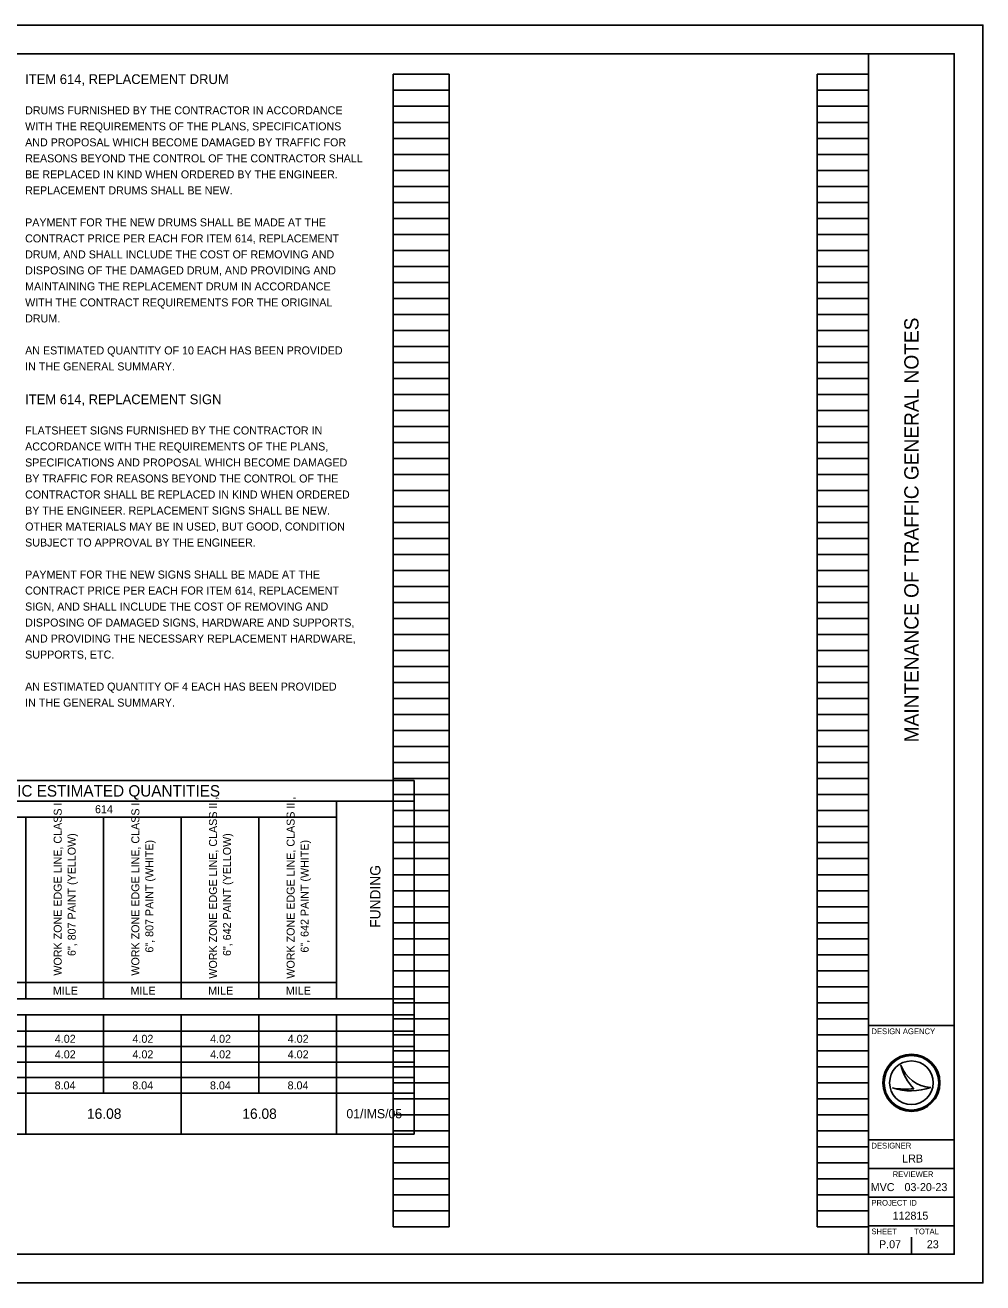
# Model space of a CAD drawing. Extents: x 0 to 154, y -283 to 22.
# Drawn here: x 17.24 to 34, y 0 to 22 of the extents above; entities that cross this region are included whole.
import ezdxf

# ---------------------------------------------------------------- set-up
doc = ezdxf.new("R2010")
doc.units = 0
for name, color, linetype in [('SH_Border', 7, 'Continuous'), ('SH_Cut_Line', 7, 'Continuous'), ('SH_Data', 7, 'Continuous'), ('SH_Text', 7, 'Continuous')]:
    doc.layers.add(name, color=color, linetype=linetype)

msp = doc.modelspace()

# ---------------------------------------------------------------- linework, layer by layer
at = {"layer": 'SH_Border'}
for p, q in [((32, 0.5), (32, 21.5)), ((32, 4.5), (33.5, 4.5)), ((32, 2.5), (33.5, 2.5)), ((32, 2), (33.5, 2)), ((32, 1.5), (33.5, 1.5)), ((32, 1), (33.5, 1))]:
    msp.add_line(p, q, dxfattribs=at)
msp.add_lwpolyline([(1.5, 21.5), (33.5, 21.5), (33.5, 0.5), (1.5, 0.5)], close=True, dxfattribs=at)
at = {"layer": 'SH_Cut_Line'}
msp.add_lwpolyline([(0, 0), (34, 0), (34, 22), (0, 22)], close=True, dxfattribs=at)
at = {"layer": 'SH_Data'}
for p, q in [((23.68, 0.98), (23.68, 21.14)), ((23.68, 21.14), (24.66, 21.14)), ((24.66, 0.98), (24.66, 21.14)), ((31.1, 0.98), (31.1, 21.14)), ((31.1, 21.14), (32, 21.14)), ((32, 0.98), (32, 21.14)), ((23.68, 20.86), (24.66, 20.86)), ((31.1, 20.86), (32, 20.86)), ((23.68, 20.58), (24.66, 20.58)), ((31.1, 20.58), (32, 20.58)), ((23.68, 20.3), (24.66, 20.3)), ((31.1, 20.3), (32, 20.3)), ((23.68, 20.02), (24.66, 20.02)), ((31.1, 20.02), (32, 20.02)), ((23.68, 19.74), (24.66, 19.74)), ((31.1, 19.74), (32, 19.74)), ((23.68, 19.46), (24.66, 19.46)), ((31.1, 19.46), (32, 19.46)), ((23.68, 19.18), (24.66, 19.18)), ((31.1, 19.18), (32, 19.18)), ((23.68, 18.9), (24.66, 18.9)), ((31.1, 18.9), (32, 18.9)), ((23.68, 18.62), (24.66, 18.62)), ((31.1, 18.62), (32, 18.62)), ((23.68, 18.34), (24.66, 18.34)), ((31.1, 18.34), (32, 18.34)), ((23.68, 18.06), (24.66, 18.06)), ((31.1, 18.06), (32, 18.06)), ((23.68, 17.78), (24.66, 17.78)), ((31.1, 17.78), (32, 17.78)), ((23.68, 17.5), (24.66, 17.5)), ((31.1, 17.5), (32, 17.5)), ((23.68, 17.22), (24.66, 17.22)), ((31.1, 17.22), (32, 17.22)), ((23.68, 16.94), (24.66, 16.94)), ((31.1, 16.94), (32, 16.94)), ((23.68, 16.66), (24.66, 16.66)), ((31.1, 16.66), (32, 16.66)), ((23.68, 16.38), (24.66, 16.38)), ((31.1, 16.38), (32, 16.38)), ((23.68, 16.1), (24.66, 16.1)), ((31.1, 16.1), (32, 16.1)), ((23.68, 15.82), (24.66, 15.82)), ((31.1, 15.82), (32, 15.82)), ((23.68, 15.54), (24.66, 15.54)), ((31.1, 15.54), (32, 15.54)), ((23.68, 15.26), (24.66, 15.26)), ((31.1, 15.26), (32, 15.26)), ((23.68, 14.98), (24.66, 14.98)), ((31.1, 14.98), (32, 14.98)), ((23.68, 14.7), (24.66, 14.7)), ((31.1, 14.7), (32, 14.7)), ((23.68, 14.42), (24.66, 14.42)), ((31.1, 14.42), (32, 14.42)), ((23.68, 14.14), (24.66, 14.14)), ((31.1, 14.14), (32, 14.14)), ((23.68, 13.86), (24.66, 13.86)), ((31.1, 13.86), (32, 13.86)), ((23.68, 13.58), (24.66, 13.58)), ((31.1, 13.58), (32, 13.58)), ((23.68, 13.3), (24.66, 13.3)), ((31.1, 13.3), (32, 13.3)), ((23.68, 13.02), (24.66, 13.02)), ((31.1, 13.02), (32, 13.02)), ((23.68, 12.74), (24.66, 12.74)), ((31.1, 12.74), (32, 12.74)), ((23.68, 12.46), (24.66, 12.46)), ((31.1, 12.46), (32, 12.46)), ((23.68, 12.18), (24.66, 12.18)), ((31.1, 12.18), (32, 12.18)), ((23.68, 11.9), (24.66, 11.9)), ((31.1, 11.9), (32, 11.9)), ((23.68, 11.62), (24.66, 11.62)), ((31.1, 11.62), (32, 11.62)), ((23.68, 11.34), (24.66, 11.34)), ((31.1, 11.34), (32, 11.34)), ((23.68, 11.06), (24.66, 11.06)), ((31.1, 11.06), (32, 11.06)), ((23.68, 10.78), (24.66, 10.78)), ((31.1, 10.78), (32, 10.78)), ((23.68, 10.5), (24.66, 10.5)), ((31.1, 10.5), (32, 10.5)), ((23.68, 10.22), (24.66, 10.22)), ((31.1, 10.22), (32, 10.22)), ((23.68, 9.94), (24.66, 9.94)), ((31.1, 9.94), (32, 9.94)), ((23.68, 9.66), (24.66, 9.66)), ((31.1, 9.66), (32, 9.66)), ((23.68, 9.38), (24.66, 9.38)), ((31.1, 9.38), (32, 9.38)), ((23.68, 9.1), (24.66, 9.1)), ((31.1, 9.1), (32, 9.1)), ((23.68, 8.82), (24.66, 8.82)), ((31.1, 8.82), (32, 8.82)), ((23.68, 8.54), (24.66, 8.54)), ((31.1, 8.54), (32, 8.54)), ((23.68, 8.26), (24.66, 8.26)), ((31.1, 8.26), (32, 8.26)), ((23.68, 7.98), (24.66, 7.98)), ((31.1, 7.98), (32, 7.98)), ((23.68, 7.7), (24.66, 7.7)), ((31.1, 7.7), (32, 7.7)), ((23.68, 7.42), (24.66, 7.42)), ((31.1, 7.42), (32, 7.42)), ((23.68, 7.14), (24.66, 7.14)), ((31.1, 7.14), (32, 7.14)), ((23.68, 6.86), (24.66, 6.86)), ((31.1, 6.86), (32, 6.86)), ((23.68, 6.58), (24.66, 6.58)), ((31.1, 6.58), (32, 6.58)), ((23.68, 6.3), (24.66, 6.3)), ((31.1, 6.3), (32, 6.3)), ((23.68, 6.02), (24.66, 6.02)), ((31.1, 6.02), (32, 6.02)), ((23.68, 5.74), (24.66, 5.74)), ((31.1, 5.74), (32, 5.74)), ((23.68, 5.46), (24.66, 5.46)), ((31.1, 5.46), (32, 5.46)), ((23.68, 5.18), (24.66, 5.18)), ((31.1, 5.18), (32, 5.18)), ((23.68, 4.9), (24.66, 4.9)), ((31.1, 4.9), (32, 4.9)), ((23.68, 4.62), (24.66, 4.62)), ((31.1, 4.62), (32, 4.62)), ((23.68, 4.34), (24.66, 4.34)), ((31.1, 4.34), (32, 4.34)), ((23.68, 4.06), (24.66, 4.06)), ((31.1, 4.06), (32, 4.06)), ((23.68, 3.78), (24.66, 3.78)), ((31.1, 3.78), (32, 3.78)), ((32.567, 3.81), (32.567, 3.81)), ((23.68, 3.5), (24.66, 3.5)), ((31.1, 3.5), (32, 3.5)), ((32.417, 3.41), (32.417, 3.41)), ((32.75, 3.5), (32.75, 3.5)), ((33.087, 3.419), (33.087, 3.419)), ((23.68, 3.22), (24.66, 3.22)), ((31.1, 3.22), (32, 3.22)), ((23.68, 2.94), (24.66, 2.94)), ((31.1, 2.94), (32, 2.94)), ((23.68, 2.66), (24.66, 2.66)), ((31.1, 2.66), (32, 2.66)), ((23.68, 2.38), (24.66, 2.38)), ((31.1, 2.38), (32, 2.38)), ((23.68, 2.1), (24.66, 2.1)), ((31.1, 2.1), (32, 2.1)), ((23.68, 1.82), (24.66, 1.82)), ((31.1, 1.82), (32, 1.82)), ((23.68, 1.54), (24.66, 1.54)), ((31.1, 1.54), (32, 1.54)), ((23.68, 1.26), (24.66, 1.26)), ((31.1, 1.26), (32, 1.26)), ((23.68, 0.98), (24.66, 0.98)), ((31.1, 0.98), (32, 0.98)), ((32.375, 0.675), (32.375, 0.675)), ((32.75, 0.5), (32.75, 0.8))]:
    msp.add_line(p, q, dxfattribs=at)
for radius in [0.5, 0.477, 0.477, 0.382]:
    msp.add_circle((32.75, 3.5), radius, dxfattribs=at)
for centre, radius, start, end in [((33.116, 3.998), 0.58, 198.9257, 198.9319), ((33.347, 3.97), 0.796, 191.6379, 191.6421), ((33.116, 3.998), 0.58, 198.9319, 267.1657), ((33.347, 3.97), 0.796, 191.6421, 226.0947), ((32.739, 4.37), 1.013, 251.4576, 290.0832), ((32.648, 4.654), 1.266, 259.4964, 259.4995), ((32.739, 4.37), 1.013, 251.4527, 251.4576), ((32.648, 4.654), 1.266, 259.4995, 276.6672)]:
    msp.add_arc(centre, radius, start, end, dxfattribs=at)
at = {"layer": 'SH_Text'}
for p, q in [((9.59, 8.785), (24.047, 8.785)), ((24.047, 8.785), (24.047, 2.601)), ((9.59, 8.427), (24.047, 8.427)), ((22.688, 8.427), (22.688, 4.97)), ((14.536, 8.144), (22.688, 8.144)), ((17.253, 8.144), (17.253, 4.97)), ((18.612, 8.144), (18.612, 4.97)), ((19.971, 8.144), (19.971, 4.97)), ((21.33, 8.144), (21.33, 4.97)), ((14.536, 5.253), (22.688, 5.253)), ((9.59, 4.97), (24.047, 4.97)), ((9.59, 4.688), (24.047, 4.688)), ((17.253, 4.688), (17.253, 2.601)), ((18.612, 4.688), (18.612, 3.318)), ((19.971, 4.688), (19.971, 2.601)), ((21.33, 4.688), (21.33, 3.318)), ((22.688, 4.688), (22.688, 2.601)), ((9.59, 4.405), (24.047, 4.405)), ((9.59, 4.133), (24.047, 4.133)), ((9.59, 3.861), (24.047, 3.861)), ((9.59, 3.59), (24.047, 3.59)), ((9.59, 3.318), (24.047, 3.318)), ((9.59, 2.601), (24.047, 2.601))]:
    msp.add_line(p, q, dxfattribs=at)

# ---------------------------------------------------------------- texts
at = {"layer": 'SH_Data'}
msp.add_text('MAINTENANCE OF TRAFFIC GENERAL NOTES', height=0.25, rotation=90, dxfattribs=at).set_placement((32.875, 9.455))
for s, height, p in [('DESIGN AGENCY', 0.1, (32.05, 4.35)), ('DESIGNER', 0.1, (32.05, 2.35)), ('LRB', 0.14, (32.589, 2.105)), ('REVIEWER', 0.1, (32.422, 1.85)), ('MVC', 0.14, (32.038, 1.605)), ('03-20-23', 0.14, (32.629, 1.605)), ('PROJECT ID', 0.1, (32.05, 1.35)), ('112815', 0.14, (32.421, 1.105)), ('SHEET', 0.1, (32.05, 0.85)), ('TOTAL', 0.1, (32.8, 0.85)), ('P.07', 0.14, (32.183, 0.605)), ('23', 0.14, (33.02, 0.605))]:
    msp.add_text(s, height=height, dxfattribs=at).set_placement(p)
at = {"layer": 'SH_Text'}
for s, height, p in [('ITEM 614, REPLACEMENT DRUM', 0.17, (17.24, 20.97)), ('DRUMS FURNISHED BY THE CONTRACTOR IN ACCORDANCE', 0.14, (17.24, 20.44)), ('WITH THE REQUIREMENTS OF THE PLANS, SPECIFICATIONS', 0.14, (17.24, 20.16)), ('AND PROPOSAL WHICH BECOME DAMAGED BY TRAFFIC FOR', 0.14, (17.24, 19.88)), ('REASONS BEYOND THE CONTROL OF THE CONTRACTOR SHALL', 0.14, (17.24, 19.6)), ('BE REPLACED IN KIND WHEN ORDERED BY THE ENGINEER.', 0.14, (17.24, 19.32)), ('REPLACEMENT DRUMS SHALL BE NEW.', 0.14, (17.24, 19.04)), ('PAYMENT FOR THE NEW DRUMS SHALL BE MADE AT THE', 0.14, (17.24, 18.48)), ('CONTRACT PRICE PER EACH FOR ITEM 614, REPLACEMENT', 0.14, (17.24, 18.2)), ('DRUM, AND SHALL INCLUDE THE COST OF REMOVING AND', 0.14, (17.24, 17.92)), ('DISPOSING OF THE DAMAGED DRUM, AND PROVIDING AND', 0.14, (17.24, 17.64)), ('MAINTAINING THE REPLACEMENT DRUM IN ACCORDANCE', 0.14, (17.24, 17.36)), ('WITH THE CONTRACT REQUIREMENTS FOR THE ORIGINAL', 0.14, (17.24, 17.08)), ('DRUM.', 0.14, (17.24, 16.8)), ('AN ESTIMATED QUANTITY OF 10 EACH HAS BEEN PROVIDED', 0.14, (17.24, 16.24)), ('IN THE GENERAL SUMMARY.', 0.14, (17.24, 15.96)), ('ITEM 614, REPLACEMENT SIGN', 0.17, (17.24, 15.37)), ('FLATSHEET SIGNS FURNISHED BY THE CONTRACTOR IN', 0.14, (17.24, 14.84)), ('ACCORDANCE WITH THE REQUIREMENTS OF THE PLANS,', 0.14, (17.24, 14.56)), ('SPECIFICATIONS AND PROPOSAL WHICH BECOME DAMAGED', 0.14, (17.24, 14.28)), ('BY TRAFFIC FOR REASONS BEYOND THE CONTROL OF THE', 0.14, (17.24, 14)), ('CONTRACTOR SHALL BE REPLACED IN KIND WHEN ORDERED', 0.14, (17.24, 13.72)), ('BY THE ENGINEER. REPLACEMENT SIGNS SHALL BE NEW.', 0.14, (17.24, 13.44)), ('OTHER MATERIALS MAY BE IN USED, BUT GOOD, CONDITION', 0.14, (17.24, 13.16)), ('SUBJECT TO APPROVAL BY THE ENGINEER.', 0.14, (17.24, 12.88)), ('PAYMENT FOR THE NEW SIGNS SHALL BE MADE AT THE', 0.14, (17.24, 12.32)), ('CONTRACT PRICE PER EACH FOR ITEM 614, REPLACEMENT', 0.14, (17.24, 12.04)), ('SIGN, AND SHALL INCLUDE THE COST OF REMOVING AND', 0.14, (17.24, 11.76)), ('DISPOSING OF DAMAGED SIGNS, HARDWARE AND SUPPORTS,', 0.14, (17.24, 11.48)), ('AND PROVIDING THE NECESSARY REPLACEMENT HARDWARE,', 0.14, (17.24, 11.2)), ('SUPPORTS, ETC.', 0.14, (17.24, 10.92)), ('AN ESTIMATED QUANTITY OF 4 EACH HAS BEEN PROVIDED', 0.14, (17.24, 10.36)), ('IN THE GENERAL SUMMARY.', 0.14, (17.24, 10.08)), ('MAINTENANCE OF TRAFFIC ESTIMATED QUANTITIES', 0.2, (13.772, 8.506)), ('614', 0.14, (18.463, 8.215)), ('MILE', 0.14, (17.726, 5.041)), ('MILE', 0.14, (19.085, 5.041)), ('MILE', 0.14, (20.444, 5.041)), ('MILE', 0.14, (21.803, 5.041)), ('4.02', 0.14, (17.76, 4.199)), ('4.02', 0.14, (19.119, 4.199)), ('4.02', 0.14, (20.478, 4.199)), ('4.02', 0.14, (21.836, 4.199)), ('4.02', 0.14, (17.76, 3.927)), ('4.02', 0.14, (19.119, 3.927)), ('4.02', 0.14, (20.478, 3.927)), ('4.02', 0.14, (21.836, 3.927)), ('8.04', 0.14, (17.757, 3.384)), ('8.04', 0.14, (19.116, 3.384)), ('8.04', 0.14, (20.475, 3.384)), ('8.04', 0.14, (21.833, 3.384)), ('16.08', 0.18, (18.323, 2.869)), ('16.08', 0.18, (21.041, 2.869)), ('01/IMS/05', 0.16, (22.862, 2.879))]:
    msp.add_text(s, height=height, dxfattribs=at).set_placement(p)
for s, height, p in [('WORK ZONE EDGE LINE, CLASS I, ', 0.14, (17.88, 5.374)), ('WORK ZONE EDGE LINE, CLASS I, ', 0.14, (19.239, 5.374)), ('WORK ZONE EDGE LINE, CLASS III, ', 0.14, (20.598, 5.321)), ('WORK ZONE EDGE LINE, CLASS III, ', 0.14, (21.956, 5.321)), ('6", 807 PAINT (YELLOW)', 0.14, (18.125, 5.717)), ('6", 807 PAINT (WHITE)', 0.14, (19.484, 5.777)), ('6", 642 PAINT (YELLOW)', 0.14, (20.843, 5.717)), ('6", 642 PAINT (WHITE)', 0.14, (22.201, 5.777)), ('FUNDING', 0.18, (23.458, 6.211))]:
    msp.add_text(s, height=height, rotation=90, dxfattribs=at).set_placement(p)

doc.saveas('drawing.dxf')
